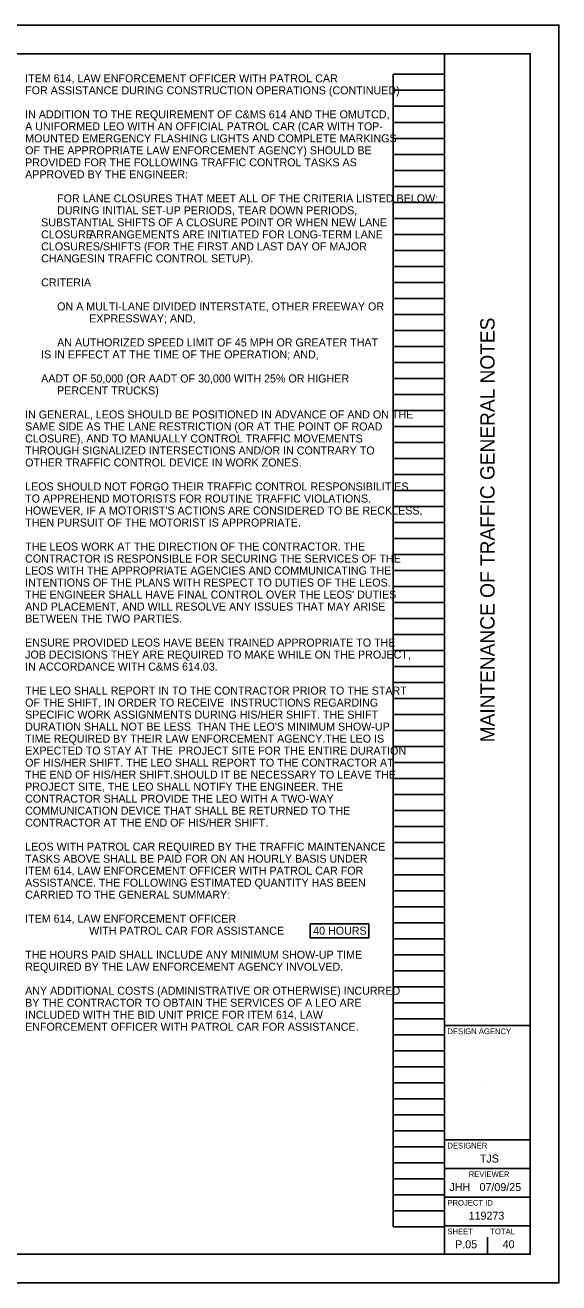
# Model space of a CAD drawing. Extents: x -14.4 to 34, y 0 to 22.
# Drawn here: x 24.66 to 34, y 0 to 22 of the extents above; entities that cross this region are included whole.
import ezdxf

# ---------------------------------------------------------------- set-up
doc = ezdxf.new("R2010")
doc.units = 0
for name, color, linetype in [('SH_Border', 7, 'Continuous'), ('SH_Cut_Line', 7, 'Continuous'), ('SH_Data', 7, 'Continuous'), ('SH_Text', 7, 'Continuous')]:
    doc.layers.add(name, color=color, linetype=linetype)

msp = doc.modelspace()

# ---------------------------------------------------------------- linework, layer by layer
at = {"layer": 'SH_Border'}
msp.add_lwpolyline([(29.648, 6.278), (30.673, 6.278), (30.673, 6.035), (29.648, 6.035)], close=True, dxfattribs=at)
at = {"layer": 'SH_Cut_Line'}
for p, q in [((31.1, 0.98), (31.1, 21.14)), ((31.1, 21.14), (32, 21.14)), ((32, 0.98), (32, 21.14)), ((31.1, 20.86), (32, 20.86)), ((31.1, 20.58), (32, 20.58)), ((31.1, 20.3), (32, 20.3)), ((31.1, 20.02), (32, 20.02)), ((31.1, 19.74), (32, 19.74)), ((31.1, 19.46), (32, 19.46)), ((31.1, 19.18), (32, 19.18)), ((31.1, 18.9), (32, 18.9)), ((31.1, 18.62), (32, 18.62)), ((31.1, 18.34), (32, 18.34)), ((31.1, 18.06), (32, 18.06)), ((31.1, 17.78), (32, 17.78)), ((31.1, 17.5), (32, 17.5)), ((31.1, 17.22), (32, 17.22)), ((31.1, 16.94), (32, 16.94)), ((31.1, 16.66), (32, 16.66)), ((31.1, 16.38), (32, 16.38)), ((31.1, 16.1), (32, 16.1)), ((31.1, 15.82), (32, 15.82)), ((31.1, 15.54), (32, 15.54)), ((31.1, 15.26), (32, 15.26)), ((31.1, 14.98), (32, 14.98)), ((31.1, 14.7), (32, 14.7)), ((31.1, 14.42), (32, 14.42)), ((31.1, 14.14), (32, 14.14)), ((31.1, 13.86), (32, 13.86)), ((31.1, 13.58), (32, 13.58)), ((31.1, 13.3), (32, 13.3)), ((31.1, 13.02), (32, 13.02)), ((31.1, 12.74), (32, 12.74)), ((31.1, 12.46), (32, 12.46)), ((31.1, 12.18), (32, 12.18)), ((31.1, 11.9), (32, 11.9)), ((31.1, 11.62), (32, 11.62)), ((31.1, 11.34), (32, 11.34)), ((31.1, 11.06), (32, 11.06)), ((31.1, 10.78), (32, 10.78)), ((31.1, 10.5), (32, 10.5)), ((31.1, 10.22), (32, 10.22)), ((31.1, 9.94), (32, 9.94)), ((31.1, 9.66), (32, 9.66)), ((31.1, 9.38), (32, 9.38)), ((31.1, 9.1), (32, 9.1)), ((31.1, 8.82), (32, 8.82)), ((31.1, 8.54), (32, 8.54)), ((31.1, 8.26), (32, 8.26)), ((31.1, 7.98), (32, 7.98)), ((31.1, 7.7), (32, 7.7)), ((31.1, 7.42), (32, 7.42)), ((31.1, 7.14), (32, 7.14)), ((31.1, 6.86), (32, 6.86)), ((31.1, 6.58), (32, 6.58)), ((31.1, 6.3), (32, 6.3)), ((31.1, 6.02), (32, 6.02)), ((31.1, 5.74), (32, 5.74)), ((31.1, 5.46), (32, 5.46)), ((31.1, 5.18), (32, 5.18)), ((31.1, 4.9), (32, 4.9)), ((31.1, 4.62), (32, 4.62)), ((31.1, 4.34), (32, 4.34)), ((31.1, 4.06), (32, 4.06)), ((31.1, 3.78), (32, 3.78)), ((31.1, 3.5), (32, 3.5)), ((32.75, 3.5), (32.75, 3.5)), ((31.1, 3.22), (32, 3.22)), ((31.1, 2.94), (32, 2.94)), ((31.1, 2.66), (32, 2.66)), ((31.1, 2.38), (32, 2.38)), ((31.1, 2.1), (32, 2.1)), ((31.1, 1.82), (32, 1.82)), ((31.1, 1.54), (32, 1.54)), ((31.1, 1.26), (32, 1.26)), ((31.1, 0.98), (32, 0.98)), ((32.375, 0.675), (32.375, 0.675)), ((32.75, 0.5), (32.75, 0.8))]:
    msp.add_line(p, q, dxfattribs=at)
at = {"layer": 'SH_Data'}
for p, q in [((32, 0.5), (32, 21.5)), ((32, 4.5), (33.5, 4.5)), ((32, 2.5), (33.5, 2.5)), ((32, 2), (33.5, 2)), ((32, 1.5), (33.5, 1.5)), ((32, 1), (33.5, 1))]:
    msp.add_line(p, q, dxfattribs=at)
msp.add_lwpolyline([(1.5, 21.5), (33.5, 21.5), (33.5, 0.5), (1.5, 0.5)], close=True, dxfattribs=at)
at = {"layer": 'SH_Text'}
msp.add_lwpolyline([(0, 0), (34, 0), (34, 22), (0, 22)], close=True, dxfattribs=at)

# ---------------------------------------------------------------- texts
at = {"layer": 'SH_Border'}
for s, p in [('ITEM 614, LAW ENFORCEMENT OFFICER WITH PATROL CAR', (24.66, 21)), ('FOR ASSISTANCE DURING CONSTRUCTION OPERATIONS (CONTINUED)', (24.66, 20.79)), ('IN ADDITION TO THE REQUIREMENT OF C&MS 614 AND THE OMUTCD, ', (24.66, 20.37)), ('A UNIFORMED LEO WITH AN OFFICIAL PATROL CAR (CAR WITH TOP-', (24.66, 20.16)), ('MOUNTED EMERGENCY FLASHING LIGHTS AND COMPLETE MARKINGS ', (24.66, 19.95)), ('OF THE APPROPRIATE LAW ENFORCEMENT AGENCY) SHOULD BE ', (24.66, 19.74)), ('PROVIDED FOR THE FOLLOWING TRAFFIC CONTROL TASKS AS ', (24.66, 19.53)), ('APPROVED BY THE ENGINEER:', (24.66, 19.32)), ('FOR LANE CLOSURES THAT MEET ALL OF THE CRITERIA LISTED BELOW:', (25.22, 18.9)), ('DURING INITIAL SET-UP PERIODS, TEAR DOWN PERIODS,', (25.22, 18.69)), ('SUBSTANTIAL SHIFTS OF A CLOSURE POINT OR WHEN NEW LANE', (24.94, 18.48)), ('CLOSURE', (24.94, 18.27)), ('ARRANGEMENTS ARE INITIATED FOR LONG-TERM LANE', (25.78, 18.27)), ('CLOSURES/SHIFTS (FOR THE FIRST AND LAST DAY OF MAJOR', (24.94, 18.06)), ('CHANGESIN TRAFFIC CONTROL SETUP).', (24.94, 17.85)), ('CRITERIA', (24.94, 17.43)), ('ON A MULTI-LANE DIVIDED INTERSTATE, OTHER FREEWAY OR', (25.22, 17.01)), ('EXPRESSWAY; AND,', (25.78, 16.8)), ('AN AUTHORIZED SPEED LIMIT OF 45 MPH OR GREATER THAT', (25.22, 16.38)), ('IS IN EFFECT AT THE TIME OF THE OPERATION; AND,', (24.94, 16.17)), ('AADT OF 50,000 (OR AADT OF 30,000 WITH 25% OR HIGHER', (24.94, 15.75)), ('PERCENT TRUCKS)', (25.22, 15.54)), ('IN GENERAL, LEOS SHOULD BE POSITIONED IN ADVANCE OF AND ON THE ', (24.66, 15.12)), ('SAME SIDE AS THE LANE RESTRICTION (OR AT THE POINT OF ROAD ', (24.66, 14.91)), ('CLOSURE), AND TO MANUALLY CONTROL TRAFFIC MOVEMENTS ', (24.66, 14.7)), ('THROUGH SIGNALIZED INTERSECTIONS AND/OR IN CONTRARY TO', (24.66, 14.49)), ('OTHER TRAFFIC CONTROL DEVICE IN WORK ZONES.', (24.66, 14.28)), ('LEOS SHOULD NOT FORGO THEIR TRAFFIC CONTROL RESPONSIBILITIES ', (24.66, 13.86)), ('TO APPREHEND MOTORISTS FOR ROUTINE TRAFFIC VIOLATIONS. ', (24.66, 13.65)), ("HOWEVER, IF A MOTORIST'S ACTIONS ARE CONSIDERED TO BE RECKLESS, ", (24.66, 13.44)), ('THEN PURSUIT OF THE MOTORIST IS APPROPRIATE.', (24.66, 13.23)), ('THE LEOS WORK AT THE DIRECTION OF THE CONTRACTOR. THE ', (24.66, 12.81)), ('CONTRACTOR IS RESPONSIBLE FOR SECURING THE SERVICES OF THE ', (24.66, 12.6)), ('LEOS WITH THE APPROPRIATE AGENCIES AND COMMUNICATING THE ', (24.66, 12.39)), ('INTENTIONS OF THE PLANS WITH RESPECT TO DUTIES OF THE LEOS. ', (24.66, 12.18)), ("THE ENGINEER SHALL HAVE FINAL CONTROL OVER THE LEOS' DUTIES ", (24.66, 11.97)), ('AND PLACEMENT, AND WILL RESOLVE ANY ISSUES THAT MAY ARISE ', (24.66, 11.76)), ('BETWEEN THE TWO PARTIES.', (24.66, 11.55)), ('ENSURE PROVIDED LEOS HAVE BEEN TRAINED APPROPRIATE TO THE ', (24.66, 11.13)), ('JOB DECISIONS THEY ARE REQUIRED TO MAKE WHILE ON THE PROJECT, ', (24.66, 10.92)), ('IN ACCORDANCE WITH C&MS 614.03.', (24.66, 10.71)), ('THE LEO SHALL REPORT IN TO THE CONTRACTOR PRIOR TO THE START ', (24.66, 10.29)), ('OF THE SHIFT, IN ORDER TO RECEIVE  INSTRUCTIONS REGARDING ', (24.66, 10.08)), ('SPECIFIC WORK ASSIGNMENTS DURING HIS/HER SHIFT. THE SHIFT ', (24.66, 9.87)), ("DURATION SHALL NOT BE LESS  THAN THE LEO'S MINIMUM SHOW-UP ", (24.66, 9.66)), ('TIME REQUIRED BY THEIR LAW ENFORCEMENT AGENCY.THE LEO IS ', (24.66, 9.45)), ('EXPECTED TO STAY AT THE  PROJECT SITE FOR THE ENTIRE DURATION ', (24.66, 9.24)), ('OF HIS/HER SHIFT. THE LEO SHALL REPORT TO THE CONTRACTOR AT ', (24.66, 9.03)), ('THE END OF HIS/HER SHIFT.SHOULD IT BE NECESSARY TO LEAVE THE ', (24.66, 8.82)), ('PROJECT SITE, THE LEO SHALL NOTIFY THE ENGINEER. THE ', (24.66, 8.61)), ('CONTRACTOR SHALL PROVIDE THE LEO WITH A TWO-WAY ', (24.66, 8.4)), ('COMMUNICATION DEVICE THAT SHALL BE RETURNED TO THE ', (24.66, 8.19)), ('CONTRACTOR AT THE END OF HIS/HER SHIFT.', (24.66, 7.98)), ('LEOS WITH PATROL CAR REQUIRED BY THE TRAFFIC MAINTENANCE ', (24.66, 7.56)), ('TASKS ABOVE SHALL BE PAID FOR ON AN HOURLY BASIS UNDER ', (24.66, 7.35)), ('ITEM 614, LAW ENFORCEMENT OFFICER WITH PATROL CAR FOR ', (24.66, 7.14)), ('ASSISTANCE. THE FOLLOWING ESTIMATED QUANTITY HAS BEEN ', (24.66, 6.93)), ('CARRIED TO THE GENERAL SUMMARY:', (24.66, 6.72)), ('ITEM 614, LAW ENFORCEMENT OFFICER ', (24.66, 6.3)), ('WITH PATROL CAR FOR ASSISTANCE', (25.78, 6.09)), ('40 HOURS', (29.7, 6.09)), ('THE HOURS PAID SHALL INCLUDE ANY MINIMUM SHOW-UP TIME ', (24.66, 5.67)), ('REQUIRED BY THE LAW ENFORCEMENT AGENCY INVOLVED.', (24.66, 5.46)), ('ANY ADDITIONAL COSTS (ADMINISTRATIVE OR OTHERWISE) INCURRED ', (24.66, 5.04)), ('BY THE CONTRACTOR TO OBTAIN THE SERVICES OF A LEO ARE ', (24.66, 4.83)), ('INCLUDED WITH THE BID UNIT PRICE FOR ITEM 614, LAW ', (24.66, 4.62)), ('ENFORCEMENT OFFICER WITH PATROL CAR FOR ASSISTANCE.', (24.66, 4.41))]:
    msp.add_text(s, height=0.14, dxfattribs=at).set_placement(p)
at = {"layer": 'SH_Cut_Line'}
msp.add_text('MAINTENANCE OF TRAFFIC GENERAL NOTES', height=0.25, rotation=90, dxfattribs=at).set_placement((32.875, 9.455))
for s, height, p in [('DESIGN AGENCY', 0.1, (32.05, 4.35)), ('DESIGNER', 0.1, (32.05, 2.35)), ('TJS', 0.14, (32.618, 2.105)), ('REVIEWER', 0.1, (32.422, 1.85)), ('JHH', 0.14, (32.087, 1.605)), ('07/09/25', 0.14, (32.611, 1.605)), ('PROJECT ID', 0.1, (32.05, 1.35)), ('119273', 0.14, (32.421, 1.105)), ('SHEET', 0.1, (32.05, 0.85)), ('TOTAL', 0.1, (32.8, 0.85)), ('P.05', 0.14, (32.185, 0.605)), ('40', 0.14, (33.017, 0.605))]:
    msp.add_text(s, height=height, dxfattribs=at).set_placement(p)

doc.saveas('drawing.dxf')
